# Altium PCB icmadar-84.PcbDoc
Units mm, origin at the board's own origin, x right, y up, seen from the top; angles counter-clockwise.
Board outline 53.54 x 34.77 mm, 2 copper layers (Top Layer, Bottom Layer); 13 components, 8 nets, 40 pads, 0 vias.
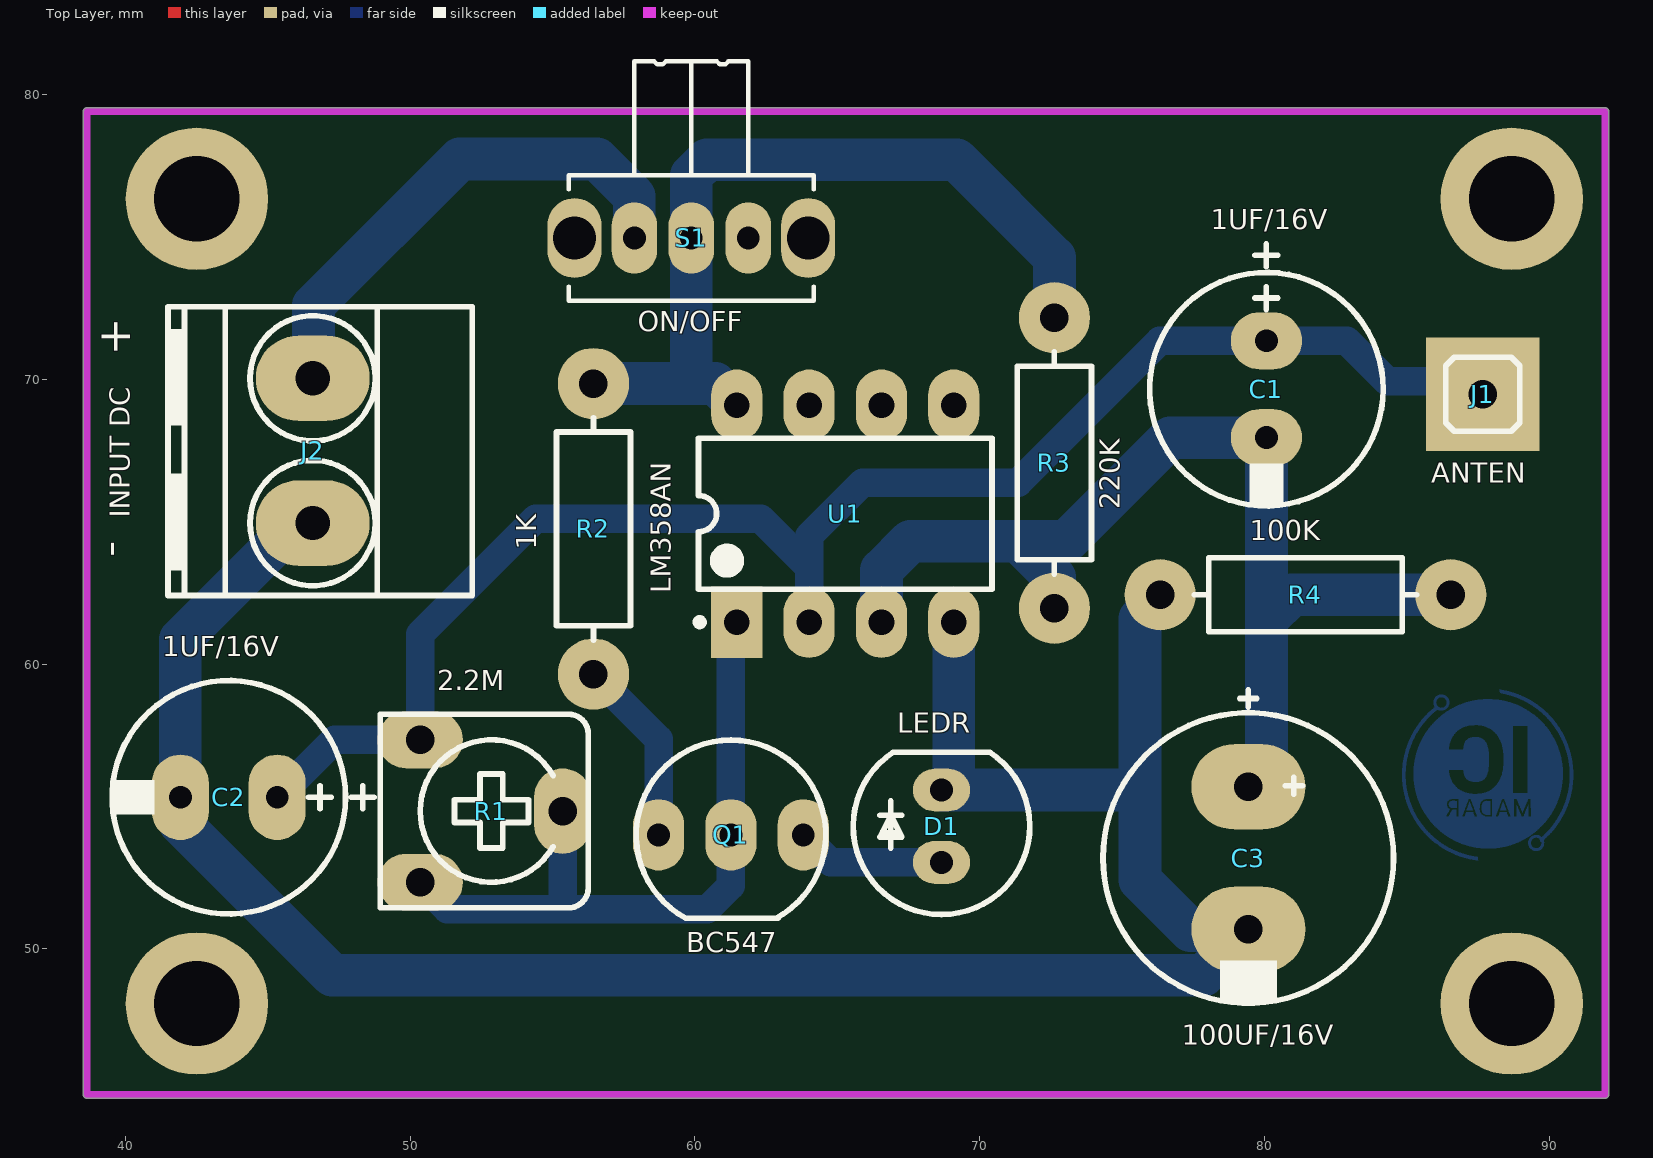
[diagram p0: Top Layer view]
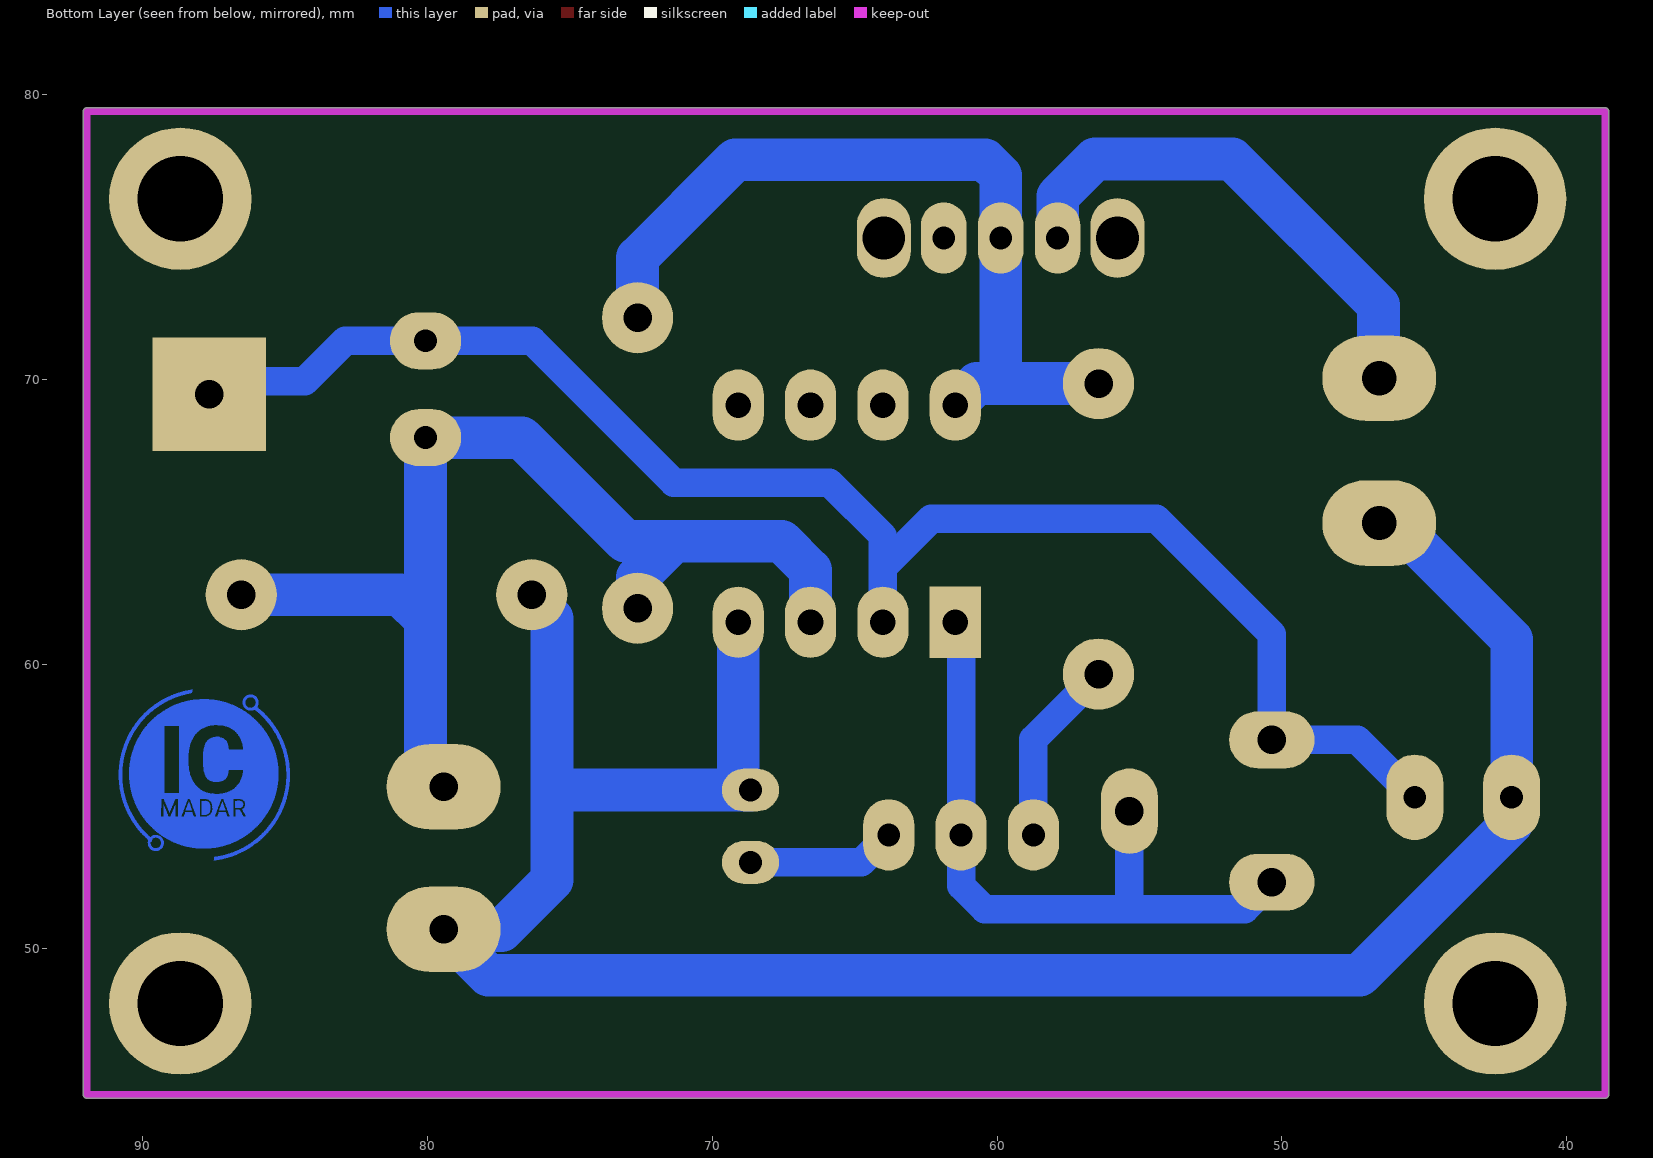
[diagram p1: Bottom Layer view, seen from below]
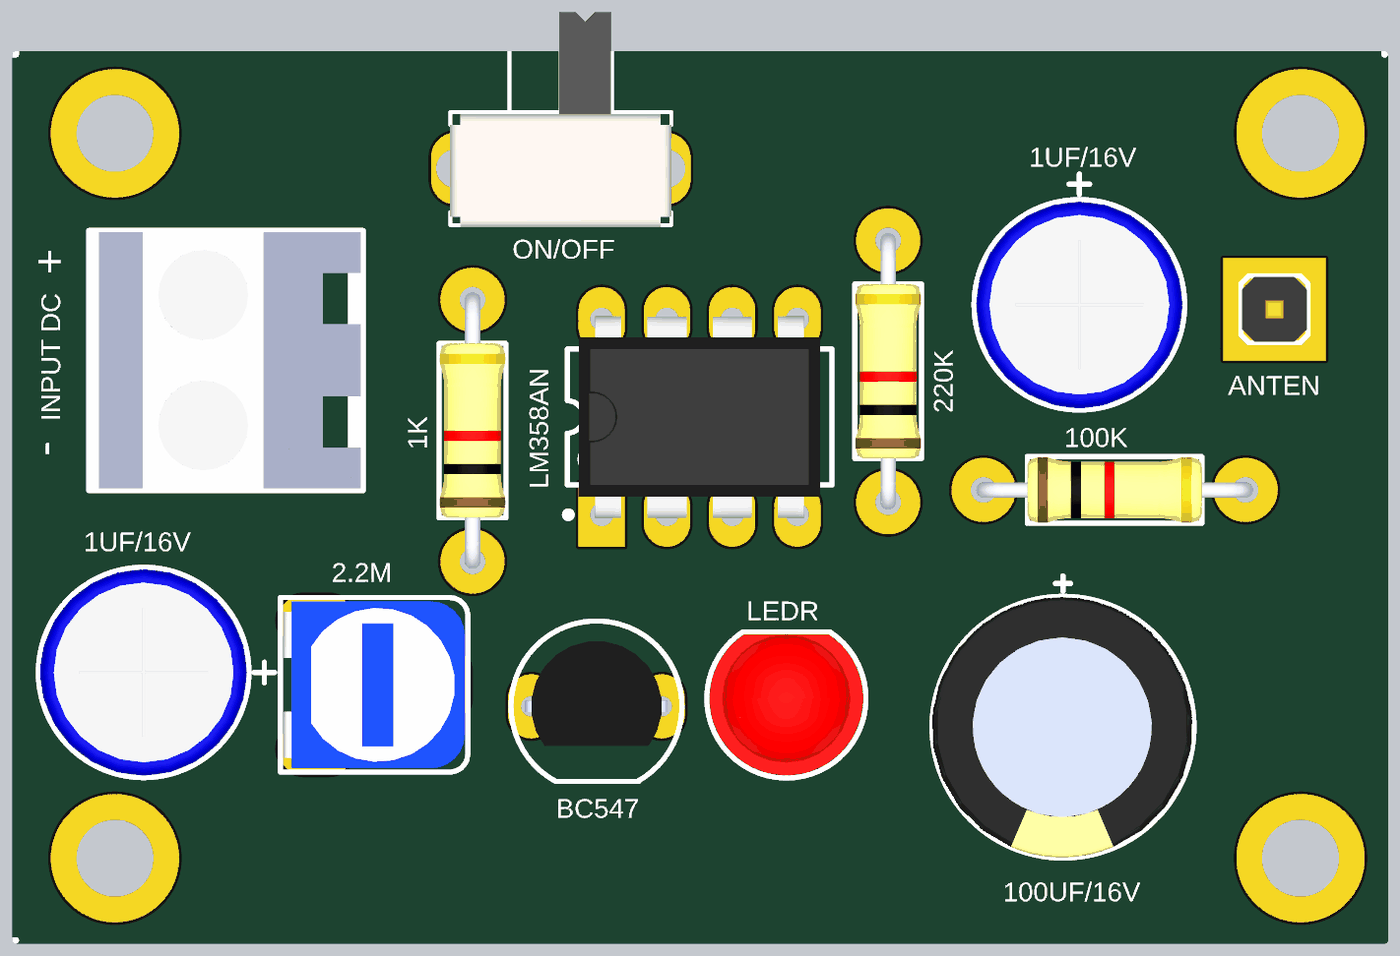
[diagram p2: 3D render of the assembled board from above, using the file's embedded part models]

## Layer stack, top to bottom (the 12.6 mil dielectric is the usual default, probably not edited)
Top Solder: solder mask 0.0102, Solder Resist, Dk 3.5
Top Layer: signal copper 0.0356
Dielectric 1: dielectric 0.32, FR-4, Dk 4.8
Bottom Layer: signal copper 0.0356
Bottom Solder: solder mask 0.0102, Solder Resist, Dk 3.5

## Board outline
38.659,44.754 cw(c38.659,44.882) 38.531,44.882 38.531,79.4 cw(c38.659,79.4) 38.659,79.528 91.948,79.528 cw(c91.948,79.4) 92.075,79.4 92.075,44.882 cw(c91.948,44.882) 91.948,44.754

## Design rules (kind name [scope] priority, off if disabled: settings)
Clearance [All] p1: gap=0.254 ignorepadtopadclearanceinfootprint=FALSE except(0: Arc-Hole Track-Hole SMDPad-Hole THPad-Hole Via-Hole Fill-Hole Poly-Hole Region-Hole Text-Hole)
PolygonConnect [All] p1: connectstyle=Relief reliefconductorwidth=0.254 reliefentries=4 polygonreliefangle="90 Angle" airgapwidth=0.254
RoutingVias [All] p1: holewidth=0.711 width=1.27 viastyle="Through Hole" minholewidth=0.711 minwidth=1.27 maxholewidth=0.711 maxwidth=1.27
SolderMaskExpansion [All] p1: expansion=0.102 istentingtop=FALSE
Width [All] p1: maxlimit=2 minlimit=0.001 preferedwidth=0.254
30 further rules are at their usual default settings.

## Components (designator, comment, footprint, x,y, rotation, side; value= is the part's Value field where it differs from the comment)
C1 "1UF/16V" C_EL_8X12#1 80.061,69.647 r270 top
C2 "1UF/16V" C_EL_8X12#2 43.637,55.321 r180 top
C3 "100UF/16V" C_EL_10X20 79.426,53.188 r270 top locked
D1 "LEDR" LED5MM_RED 68.656,54.305 r90 top
J1 "ANTEN" HDR_M_1 87.655,69.469 r0 top
J2 "INPUT DC" TBG_2 46.584,67.488 r90 top
Q1 "BC547" SOT54 61.265,54 r270 top
R1 "2.2M" POT_7X5 52.857,54.839 r270 top
R2 "1K" R025W_AX04 56.439,64.745 r90 top
R3 "220K" R025W_AX04 72.619,67.056 r90 top
R4 "100K" R025W_AX04 81.432,62.433 r0 top
S1 "ON/OFF" "SPDT Subminiator" 59.874,74.955 r0 top
U1 "LM358AN" N08E 65.278,65.278 r90 top

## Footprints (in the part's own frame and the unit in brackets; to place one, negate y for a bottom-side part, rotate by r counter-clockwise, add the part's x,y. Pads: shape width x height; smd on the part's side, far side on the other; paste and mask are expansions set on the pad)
C_EL_8X12#1 [mm] "Cap Elec, D8.0X12.0H pitch: 3.5mm, RB.14/.26, RB.15/.32"
  oval 2x2.5 hole 0.8: 1(-1.7,0) 2(1.7,0)
  silkscreen extent -5.1,-4.1 4.1,4.1, body extent -4.02,-4.03 4.03,4.03, height 2.98
C_EL_8X12#2 [mm] "Cap Elec, D8.0X12.0H pitch: 3.5mm, RB.14/.26, RB.15/.32"
  oval 2x3 hole 0.8: 1(-1.7,0) 2(1.7,0)
  silkscreen extent -5.1,-4.1 4.1,4.1, body extent -4.02,-4.03 4.03,4.03, height 2.98
C_EL_10X20 [mm] "Cap Elec, D10.0X20.0H pitch: 5.0mm, RB.2/.4"
  oval 3x4 hole 1: 1(-2.5,0) 2(2.5,0)
  silkscreen extent -5.9,-5.1 5.1,5.1, body extent -5.08,-5.1 5.08,5.04, height 20.62
HDR_M_1 [mm] "Connector; Header; 1 Position"
  rect 4x4 hole 1 mask+0.1: 1(0,0)
  silkscreen extent -1.3,-1.3 1.3,1.3, body extent -1.27,-1.27 1.27,1.27, height 8.54
LED5MM_RED [mm] "LED THD 5MM RED"
  oval 1.5x2 hole 0.8: 1(-1.27,0) 2(1.27,0)
  silkscreen extent -3.1,-3.1 2.6,3.1, body extent -3,-3 2.5,3, height 9.14
N08E [mm] "DIP, 8-Leads, Row Spacing 7.62mm, Pitch 2.54mm, Body 9.91x6.35mm"
  rect 2.5x1.8 hole 0.9: 1(-3.81,3.81)
  oval 2.5x1.8 hole 0.9: 2(-3.81,1.27) 3(-3.81,-1.27) 4(-3.81,-3.81) 5(3.81,-3.81) 6(3.81,-1.27) 7(3.81,1.27) 8(3.81,3.81)
  silkscreen extent -3.93,-5.15 2.65,5.23, body extent -3.94,-4.7 3.93,4.7, height 4.36
POT_7X5 [mm] "POT, TRIM, 7.5X5.0mm, pitch: 5.0mm"
  oval 2x3 hole 1: 1(-2.5,-2.5) 3(2.5,-2.5)
  oval 3x2 hole 1: 2(0,2.5)
  silkscreen extent -3.4,-3.9 3.4,3.4, body extent -3.25,-3.78 3.25,3.27, height 7
R025W_AX04 [mm] "RESISTOR 1/4 WATT, AXIAL0.4"
  round 2.5 hole 1: 1(-5.1,0) 2(5.1,0)
  silkscreen extent -3.9,-1.3 3.9,1.3, body extent -5.38,-1.28 5.38,1.28, height 2.6
SOT54 [mm] "TO, Flat Index; 3 In-Line, Axial Leads; Body Dia. 4.6mm; Leads 0.48 x 0.45 mm (max)"
  oval 2.5x1.8 hole 0.8: 1(0,2.54) 2(0,0) 3(0,-2.54)
  silkscreen extent -3.33,-3.33 2.93,3.33, body extent -2.55,-2.77 1.55,2.77, height 7.7
"SPDT Subminiator" [mm] "Subminiator SPDT switch"
  oval 1.6x2.5 hole 0.8: 1(2,0) 2(0,0) 3(-2,0)
  oval 1.9x2.8 hole 1.5: M2(-4.1,0) M2(4.1,0)
  silkscreen extent -4.3,-2.2 4.3,6.2, body extent -4.31,-2.28 4.3,6.09, height 4.7
TBG_2 [mm] "Terminal Block Green"
  oval 3x4 hole 1.2: 1(-2.54,0) 2(2.54,0)
  silkscreen extent -5.08,-5.6 5.05,5.08, body extent -5,-5.5 5,5, height 14

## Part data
C1 C2 C3: library part CAP_THD_EL, "CAP, THD, ELEC,"
D1: library part LED_THD_5MM_RED, "LED, THD, 5MM, RED"
J1: library part HDR_M_1, "CONN, HEADER, Male, pitch: 2.54mm, 1POS"
J2: library part CONN_TB2, "CONN, TERMINAL BLOCK, 5.08mm pitch"
Q1: "NPN General-purpose Transistor"
R1: library part RES_THD_POT_7X5, "RESISTOR, THD, Potentiometer"
R2 R3 R4: library part RES_THD, "RESISTOR, THD"
S1: library part "Switch SPDT_Subminiator", "Subminiator SPDT Switch"
U1: "Low Power Dual Operational Amplifier, 8-pin MDIP"

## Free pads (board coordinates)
  round 5 hole 3: 2(42.52,76.327) 3(42.52,48.082) 4(88.671,48.082) 5(88.671,76.327)

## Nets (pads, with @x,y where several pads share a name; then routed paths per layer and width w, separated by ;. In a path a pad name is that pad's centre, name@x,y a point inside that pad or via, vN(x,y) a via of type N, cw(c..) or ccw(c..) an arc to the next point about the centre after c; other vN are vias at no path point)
GND: C2.2 C3.2 D1.2 J2.1 R4.1 U1.4 | length 80.2
  Bottom Layer w1.5: C2.2 41.937,60.86 J2.1@46.609,65.532 ; C2.2 41.937,54.405 47.269,49.073 77.851,49.073 79.426,50.648 77.394,50.648 75.621,52.42 75.621,55.575 ; U1.4 69.088,56.007 D1.2 75.621,55.575 ; R4.1@75.621,61.595 75.621,55.575
NetC1_1: C1.1 C2.1 J1.1 R1.1 U1.2 | length 55.9
  Bottom Layer w1: C2.1 47.354,57.339 R1.1 50.357,61.051 54.407,65.1 62.306,65.1 64.008,63.398 ; U1.2 64.008,63.398 ; J1.1 87.198,69.926 84.303,69.926 82.882,71.347 C1.1 76.325,71.347 71.349,66.37 65.888,66.37 64.008,64.491 64.008,63.398
NetC1_2: C1.2 C3.1 R3.1 R4.2 U1.3 | length 39.5
  Bottom Layer w1.5: U1.3 66.548,63.297 67.564,64.313 71.349,64.313 ; R3.1 72.619,63.043 71.349,64.313 ; C3.1@79.426,55.728 80.061,56.362 80.061,61.544 ; R4.2 80.95,62.433 80.061,61.544 ; 71.349,64.313 73.05,64.313 76.684,67.947 C1.2 80.061,61.544
NetD1_1: D1.1 Q1.1 | length 5.3
  Bottom Layer w1: Q1.1 64.77,53.035 D1.1
NetJ2_2: J2.2 S1.3 | length 17.4
  Bottom Layer w1.5: J2.2@46.609,70.612 46.609,72.593 51.74,77.724 56.566,77.724 57.874,76.415 S1.3
NetQ1_2: Q1.2 R1.2 R1.3 U1.1 | length 24.5
  Bottom Layer w1: R1.3 51.312,51.384 55.22,51.384 ; R1.2 55.357,51.522 55.22,51.384 ; U1.1 61.265,61.265 Q1.2 61.265,52.222 60.427,51.384 55.22,51.384
NetQ1_3: Q1.3 R2.1 | length 6.6
  Bottom Layer w1: R2.1 58.725,57.359 Q1.3
VCC: R2.2 R3.2 S1.2 U1.8 | length 29.5
  Bottom Layer w1.5: R2.2 59.817,69.845 ; U1.8 60.711,69.845 59.817,69.845 ; R3.2@72.37,71.907 R3.2 72.619,74.27 69.19,77.699 60.427,77.699 59.874,77.146 S1.2 59.874,69.902 59.817,69.845
pads on no net: S1.1 S1.M2 U1.5 U1.6 U1.7

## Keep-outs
Keep-Out Layer:
  lines w0.254: 38.659,44.882 91.948,44.882 91.948,79.4 38.659,79.4 38.659,44.882

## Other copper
Bottom Layer:
  region: 88.309,54.987 88.314,55.001 88.318,55.018 88.322,55.022 88.328,55.036 88.33,55.052 88.336,55.057 88.341,55.079 88.344,55.087 88.352,55.106 88.355,55.125 88.363,55.144 88.365,55.154 88.369,55.158 88.376,55.157 88.381,55.136 88.39,55.117 88.392,55.106 88.399,55.088 88.403,55.084 88.407,55.064 88.419,55.036 88.422,55.022 88.43,55.004 88.443,54.969 88.446,54.958 88.454,54.939 88.457,54.928 88.464,54.911 88.468,54.907 88.473,54.885 88.478,54.88 88.476,54.872 88.464,54.868 88.404,54.87 88.267,54.873 88.266,54.88 88.277,54.891 88.279,54.909 88.287,54.928 88.291,54.943 88.301,54.961 88.303,54.979 88.307,54.986
  region: 86.668,55.193 86.738,55.191 86.742,55.187 86.739,54.955 86.735,54.951 86.668,54.954 86.563,54.956 86.555,54.959 86.536,54.962 86.531,54.967 86.525,54.97 86.501,54.989 86.494,54.996 86.486,55.009 86.481,55.014 86.474,55.043 86.468,55.057 86.47,55.095 86.476,55.109 86.48,55.126 86.484,55.136 86.503,55.16 86.509,55.166 86.515,55.169 86.531,55.18 86.546,55.184 86.56,55.191 86.587,55.193 86.665,55.193
  region: 87.219,55.106 87.221,55.092 87.229,55.074 87.232,55.063 87.243,55.039 87.247,55.024 87.254,55.009 87.259,54.987 87.27,54.963 87.272,54.95 87.278,54.944 87.282,54.93 87.285,54.916 87.289,54.912 87.294,54.899 87.297,54.885 87.302,54.88 87.299,54.872 87.295,54.868 87.212,54.87 87.092,54.872 87.091,54.878 87.097,54.885 87.1,54.896 87.104,54.911 87.108,54.915 87.114,54.934 87.116,54.944 87.122,54.95 87.124,54.961 87.128,54.978 87.138,54.996 87.142,55.016 87.151,55.033 87.154,55.049 87.162,55.063 87.165,55.074 87.167,55.087 87.173,55.092 87.176,55.103 87.178,55.122 87.186,55.141 87.19,55.156 87.198,55.158 87.202,55.154 87.208,55.13 87.216,55.111 87.217,55.107
  region: 87.913,54.74 87.916,54.721 87.912,54.712 87.901,54.709 87.874,54.712 87.761,54.714 87.737,54.725 87.726,54.728 87.721,54.73 87.713,54.738 87.694,54.749 87.679,54.761 87.675,54.765 87.671,54.767 87.668,54.772 87.664,54.779 87.659,54.782 87.653,54.795 87.647,54.804 87.641,54.818 87.63,54.842 87.626,54.868 87.624,54.889 87.62,54.893 87.617,54.912 87.62,55.012 87.622,55.02 87.625,55.039 87.628,55.047 87.63,55.057 87.633,55.074 87.641,55.092 87.649,55.106 87.655,55.111 87.657,55.122 87.699,55.164 87.734,55.18 87.753,55.188 87.764,55.191 87.783,55.193 87.912,55.191 87.916,55.179 87.913,55.16 87.913,54.742
  region: 881 vertices and 1 holes, not listed, extent 88.242,53.441 90.831,59.094
  region: 907 vertices and 7 holes, not listed, extent 85.229,53.527 90.465,58.766
  region: 903 vertices and 1 holes, not listed, extent 84.828,53.113 87.499,58.924

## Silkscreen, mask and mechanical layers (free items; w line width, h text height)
Top Overlay:
  text "+" at 40.564,70.815 h2 r90
  text "-" at 40.361,63.754 h2 r90

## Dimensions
38.659,79.4 to 38.659,44.882 on Top Overlay
91.948,79.4 to 38.659,79.4 on Top Overlay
